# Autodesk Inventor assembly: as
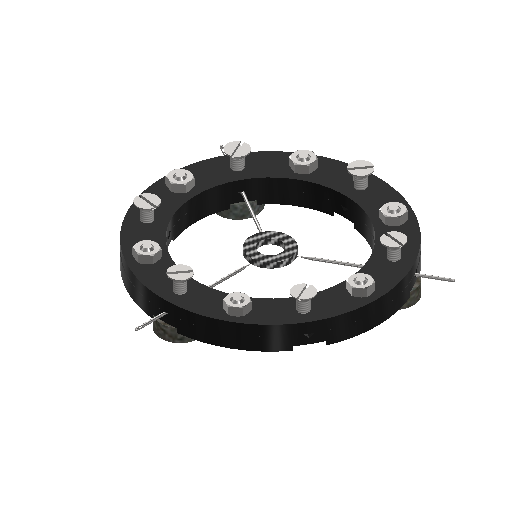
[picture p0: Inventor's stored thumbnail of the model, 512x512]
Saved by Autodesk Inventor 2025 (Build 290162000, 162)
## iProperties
Created: 2025-01
Part Number: as
Document SubType Name: Assembly
Designer: dansp
Author: dansp
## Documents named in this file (9)
- C:\Users\dansp\Desktop\Model\Model\SESTAVA.iam
- C:\Users\dansp\Desktop\Model\Model\HORNI_CAST.ipt
- C:\Users\dansp\Desktop\Model\Model\MAGNET.ipt
- C:\Users\dansp\Desktop\Model\Model\UPINACI_PRVEK.ipt
- C:\Users\dansp\Desktop\Model\Model\SPODNI_CAST.ipt
- C:\Users\dansp\Desktop\Model\Model\SROUB_SPOJ.ipt
- C:\Users\dansp\Desktop\Model\Model\MATICE_SPOJ.ipt
- C:\Users\dansp\Desktop\Model\Model\SROUB.ipt
- C:\Users\dansp\Desktop\Model\Model\TESNENI.ipt
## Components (27 placed, 8 different names)
1. HORNI_CAST:1 — Mate:1, Flush:1, Mate:2, Flush:2, Tangent:1, Tangent:2, Mate:4, Mate:5, Mate:7, Mate:8, Mate:9, Mate:14, Mate:15
2. SPODNI_CAST:1 — Mate:4, Mate:5, Mate:6, Mate:11, Mate:12, Mate:13
3. TESNENI:1 — Mate:14, Mate:15
4. UPINACI_PRVEK:1 — Tangent:1, Tangent:2
5. UPINACI_PRVEK:2
6. UPINACI_PRVEK:3
7. MAGNET:1 — Flush:2, Mate:7
8. MAGNET:2
9. MAGNET:3
10. SROUB_SPOJ:1 — Mate:8, Mate:9, Mate:10
11. MATICE_SPOJ:1 — Mate:10, Mate:11
12. SROUB_SPOJ:2
13. MATICE_SPOJ:2
14. SROUB_SPOJ:3
15. MATICE_SPOJ:3
16. SROUB_SPOJ:4
17. MATICE_SPOJ:4
18. SROUB_SPOJ:5
19. MATICE_SPOJ:5
20. SROUB_SPOJ:6
21. MATICE_SPOJ:6
22. SROUB:1 — Mate:12, Mate:13
23. SROUB:2
24. SROUB:3
25. SROUB:4
26. SROUB:5
27. SROUB:6
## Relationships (18: Mate 14, Flush 2, Tangent 2)
- Mate:1: HORNI_CAST:1
- Flush:1: HORNI_CAST:1
- Mate:2: HORNI_CAST:1
- Flush:2: HORNI_CAST:1 ↔ MAGNET:1
- Tangent:1: HORNI_CAST:1 ↔ UPINACI_PRVEK:1
- Tangent:2: HORNI_CAST:1 ↔ UPINACI_PRVEK:1
- Mate:4: HORNI_CAST:1 ↔ SPODNI_CAST:1
- Mate:5: HORNI_CAST:1 ↔ SPODNI_CAST:1
- Mate:6: SPODNI_CAST:1
- Mate:7: HORNI_CAST:1 ↔ MAGNET:1
- Mate:8: HORNI_CAST:1 ↔ SROUB_SPOJ:1
- Mate:9: HORNI_CAST:1 ↔ SROUB_SPOJ:1
- Mate:10: SROUB_SPOJ:1 ↔ MATICE_SPOJ:1
- Mate:11: SPODNI_CAST:1 ↔ MATICE_SPOJ:1
- Mate:12: SPODNI_CAST:1 ↔ SROUB:1
- Mate:13: SPODNI_CAST:1 ↔ SROUB:1
- Mate:14: HORNI_CAST:1 ↔ TESNENI:1
- Mate:15: HORNI_CAST:1 ↔ TESNENI:1
